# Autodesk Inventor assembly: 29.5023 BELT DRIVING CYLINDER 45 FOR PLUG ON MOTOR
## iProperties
Created: 2007-04
Part Number: 29.5023 BELT DRIVING CYLINDER 45 FOR PLUG ON MOTOR
Document SubType Name: Assembly
Designer: Andy Moles
Author: Andy Moles
